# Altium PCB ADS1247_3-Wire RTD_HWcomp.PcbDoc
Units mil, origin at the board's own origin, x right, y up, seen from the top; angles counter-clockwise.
Board outline 1500 x 2000 mil, 2 copper layers (TopLayer, BottomLayer); 40 components, 32 nets, 123 pads, 60 vias.
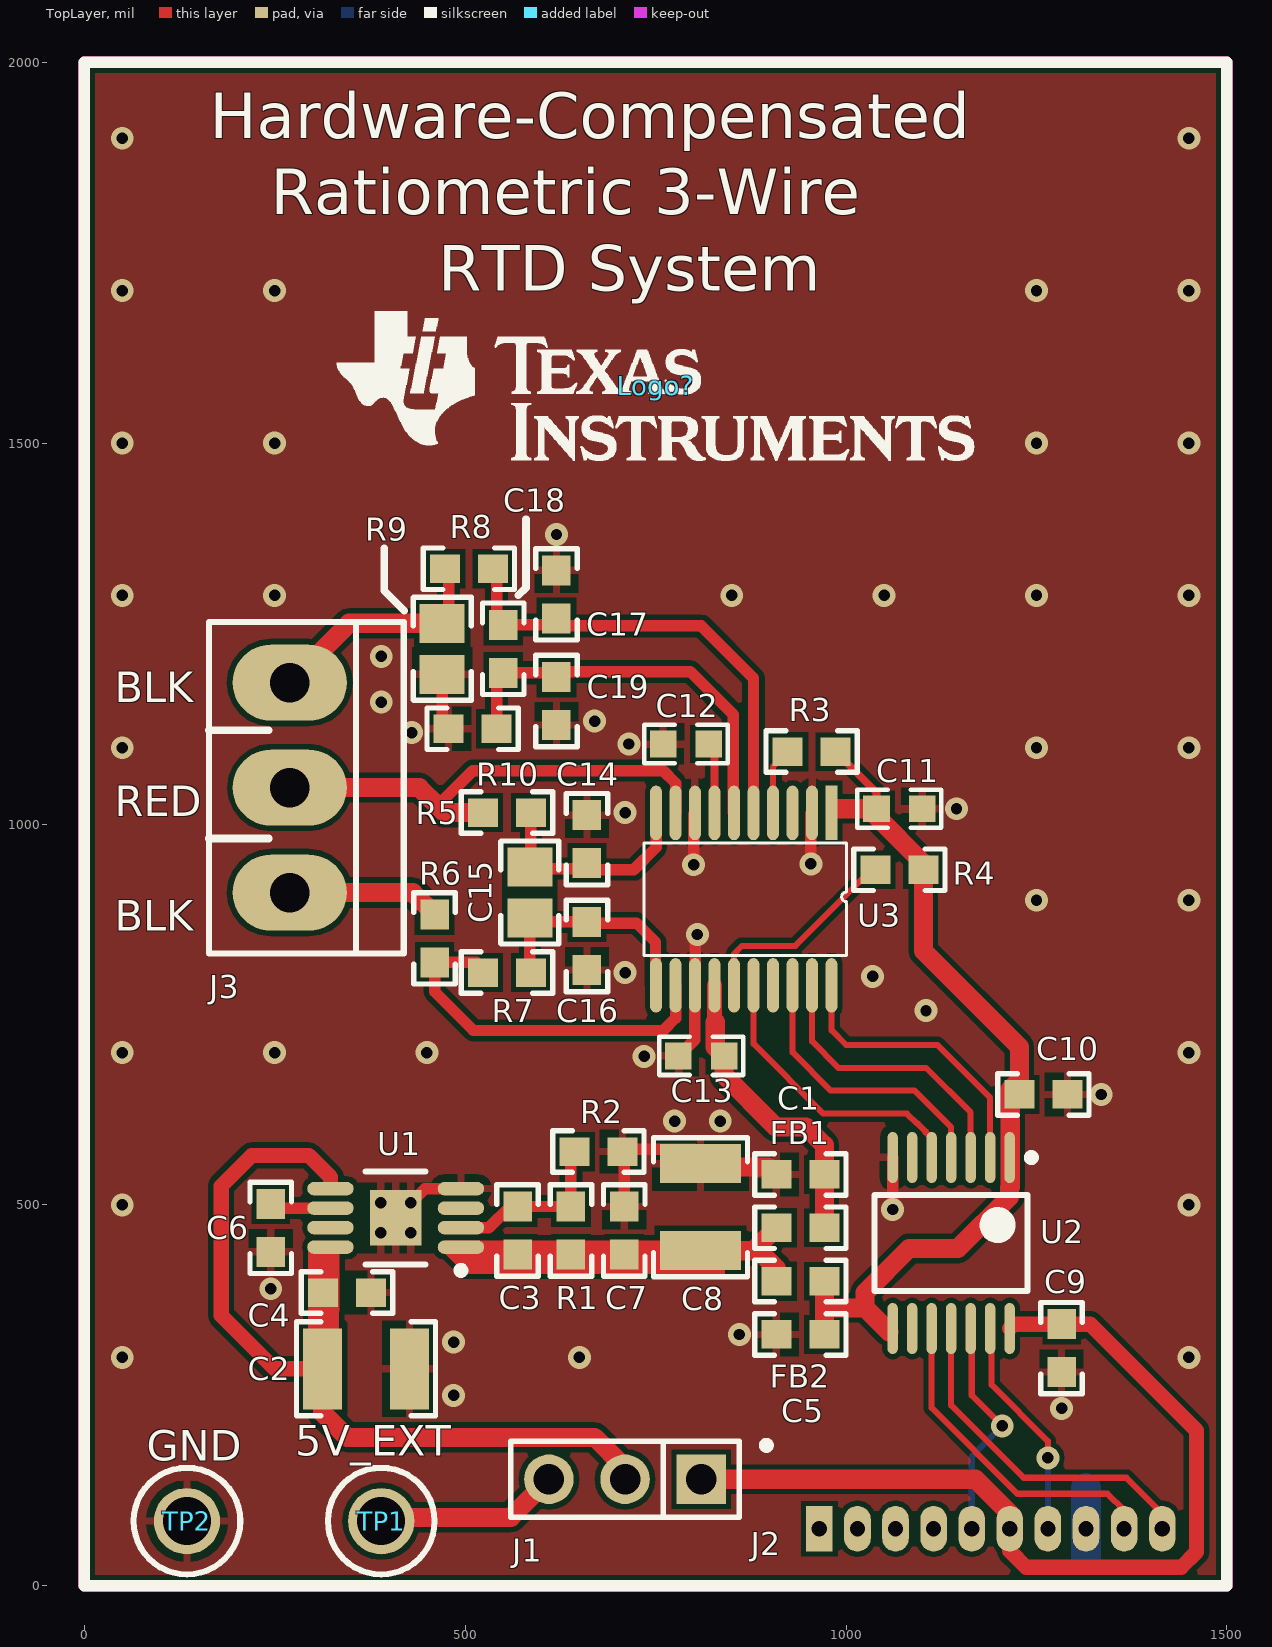
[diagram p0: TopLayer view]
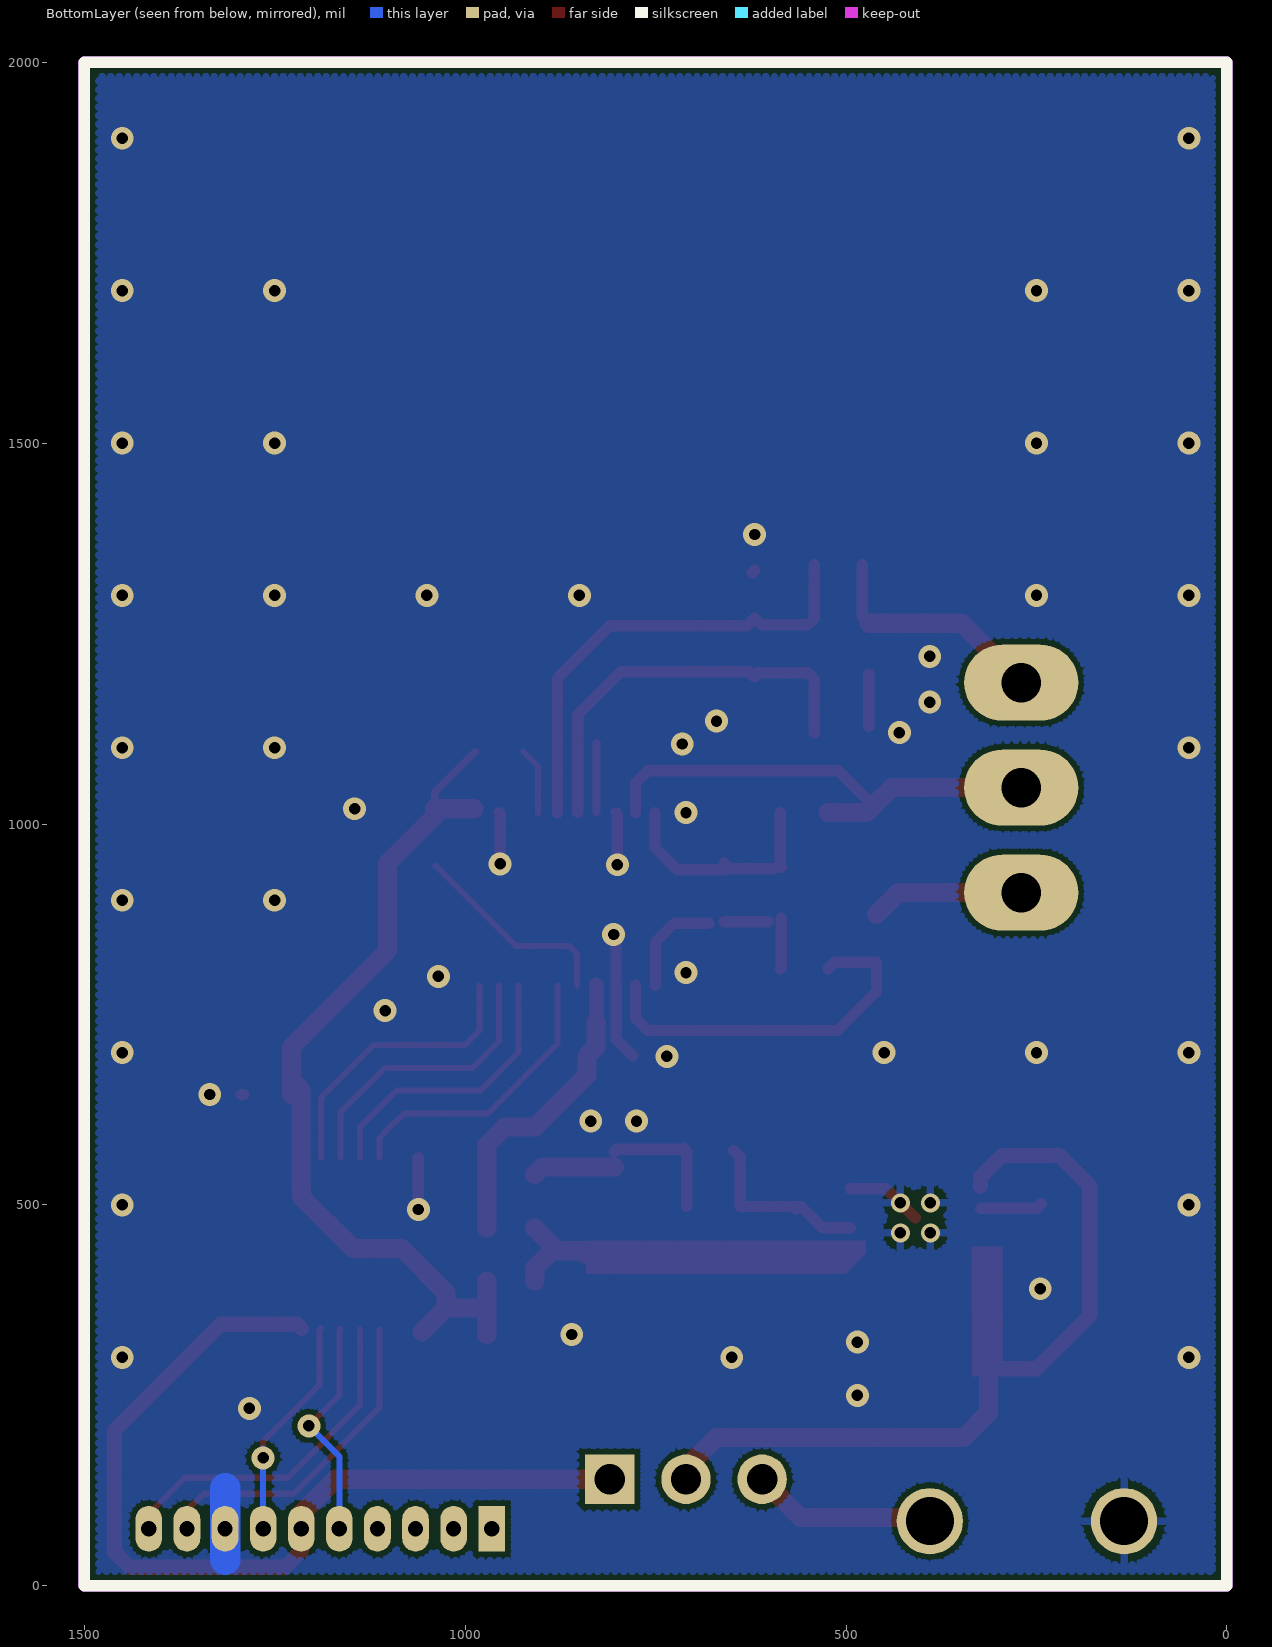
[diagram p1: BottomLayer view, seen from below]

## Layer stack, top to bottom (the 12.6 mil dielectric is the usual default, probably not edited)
TopLayer: signal copper 1.4
Dielectric: dielectric 12.6, FR-4, Dk 4.8
BottomLayer: signal copper 1.4

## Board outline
0,0 1500,0 1500,2000 0,2000

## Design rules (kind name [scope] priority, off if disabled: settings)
Clearance [All] p1: gap=7
ComponentClearance [All] p1: gap=7 collisioncheckmode=3 verticalgap=10 showdistances=FALSE
FabricationTestPointUsage TestPointUsage [All] p1: valid=0 allowmultiple=FALSE
FabricationTestpoint Testpoint [All] p1: side=3 testpointundercomponent=TRUE minsize=40 maxsize=100 preferedsize=60 minholesize=20 maxholesize=40 preferedholesize=32 testpointgrid=1 allowsidetop=TRUE allowsidebottom=TRUE usegrid=TRUE gridtolerance=0.01
PolygonConnect PolygonConnect_1 [(InComponentClass('All Components'))] p1: connectstyle=Relief reliefconductorwidth=10 reliefentries=4 polygonreliefangle="90 Angle" airgapwidth=10
PolygonConnect [All] p2: connectstyle=Direct reliefconductorwidth=15 reliefentries=4 polygonreliefangle="90 Angle" airgapwidth=7
RoutingVias [All] p1: holewidth=28 width=50 viastyle="Through Hole" minholewidth=28 minwidth=50 maxholewidth=28 maxwidth=50
SilkscreenOverComponentPads [All] p1: minsilkscreentomaskgap=10
SolderMaskExpansion [All] p1: expansion=4
Width [All] p1: maxlimit=200 minlimit=6 preferedwidth=12
24 further rules are at their usual default settings.

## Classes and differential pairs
component class Logo: Logo?
component class Header: J1

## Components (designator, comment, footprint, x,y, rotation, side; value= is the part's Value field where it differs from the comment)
C1 "GRM188R71H104KA93D" 0603#1 940,540 r180 top
C2 "C3225X7R1E106M" 1210 370,285 r0 top
C3 "C0603C103J5RACTU" 0603#1 569,466.5 r90 top
C4 "GRM188R71H104KA93D" 0603#1 345,385 r0 top
C5 "GRM188R71H104KA93D" 0603#1 940,330 r180 top
C6 "C0603C103J5RACTU" 0603#1 245,470 r270 top
C7 "GRM188R71H104KA93D" 0603#1 709,466.5 r90 top
C8 "C3225X7R1E106M" 1210 809,497 r90 top
C9 "GRM188R71H104KA93D" 0603#1 1283,312 r270 top
C10 "GRM188R71H104KA93D" 0603#1 1259,645 r0 top
C11 "GRM188R71H104KA93D" 0603#2 1070,1020 r180 top
C12 "C1608X7R1C105K" 0603#2 790,1105 r0 top
C13 "GRM188R71H104KA93D" 0603#2 810,695.59 r0 top
C14 "CL10C332JA8NNNC" 0603#1 660,980 r270 top
C15 "C2012C0G1E333J125AA" 0805 585,910 r90 top
C16 "CL10C332JA8NNNC" 0603#1 660,840 r90 top
C17 "GRM1885C1E152JA01D" 0603#1 620,1301.5 r270 top
C18 "C0603C153J3GACTU" 0603#1 550,1230 r270 top
C19 "GRM1885C1E152JA01D" 0603#1 620,1161.5 r90 top
FB1 "BLM18HG601SN1D" 0603#1 940,470 r0 top
FB2 "BLM18HG601SN1D" 0603#1 940,400 r0 top
J1 "TSW-103-07-G-S" TSW-103-07-G-S 710,140 r180 top
J2 "CON10" "DIP - 0.5 - 10" 965.24,75 r90 top
J3 "3POS_JUMPER" 3TERM_SCREW_CON_3.5MM 270,910 r90 top
Logo? "Texas Instruments" TI_Stacked_Overlay_Small 750,1575 r0 top
R1 "ERA-3AEB1653V" 0603#1 639,466.5 r90 top
R2 "RG1608P-5112-B-T5" 0603#1 675,570 r180 top
R3 "CRCW06031K00JNEA" 0603#1 955,1095 r0 top
R4 "CRCW06031K00JNEA" 0603#1 1070,940 r0 top
R5 "RC0603FR-0710KL" 0603#1 555,1015 r0 top
R6 "RG1608P-121-B-T5" 0603#1 460,850 r270 top
R7 "RC0603FR-0710KL" 0603#1 555,805 r0 top
R8 "RC0603FR-0720KL" 0603#1 505,1335 r180 top
R9 "RG2012L-332-L-T05" 0805 470,1230 r90 top
R10 "RC0603FR-0720KL" 0603#1 510,1125 r180 top
TP1 "5V_EXT" Keystone5005 390,85 r270 top
TP2 "GND" Keystone5006 135,85 r0 top
U1 "TPS7A4901" MUY08A_N 409,483 r180 top
U2 "TXS0104E" MTC14_N 1138,450 r270 top
U3 "ADS1247" 20-TSSOP(PW) 981,1014.59 r270 top

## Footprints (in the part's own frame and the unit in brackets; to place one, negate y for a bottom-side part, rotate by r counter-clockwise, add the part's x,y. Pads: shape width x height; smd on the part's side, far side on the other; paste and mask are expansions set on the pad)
3TERM_SCREW_CON_3.5MM [mil]
  oval 100x150 hole 52: 1(0,0) 2(137.79,0) 3(275.59,0)
  silkscreen extent -80,-150 355,106
20-TSSOP(PW) [mm] "TSOP, 8-Leads, Body 3x3mm, Pitch 0.65mm, Exposed Pad, IPC Medium Density"
  rect 1.82x0.39 smd: 1(0,0)
  oval 1.82x0.39 smd: 2(0,-0.65) 3(0,-1.3) 4(0,-1.95) 5(0,-2.6) 6(0,-3.25) 7(0,-3.9) 8(0,-4.55) 9(0,-5.2) 10(0,-5.85) 11(5.75,-5.85) 12(5.75,-5.2) 13(5.75,-4.55) 14(5.75,-3.9) 15(5.75,-3.25) 16(5.75,-2.6) 17(5.75,-1.95) 18(5.75,-1.3) 19(5.75,-0.65) 20(5.75,0)
  silkscreen extent 1,-6.25 4.75,0.5
0603#1 [mm] "0603 from SM-752 data"
  rect 1x0.95 smd: 1(-0.8,0) 2(0.8,0)
  silkscreen extent -1.52,-0.69 1.52,0.69, body extent -0.87,-0.47 0.87,0.47, height 0.85
0603#2 [mm]
  rect 0.889x0.889 smd: 1(-0.762,0) 2(0.762,0)
  silkscreen extent -1.4,-0.64 1.4,0.64
0805 [mm] "0805 from SM-752 data"
  rect 1.3x1.5 smd: 1(-0.85,0) 2(0.85,0)
  silkscreen extent -1.72,-0.97 1.72,0.97, body extent -1.1,-0.72 1.1,0.72, height 1.1
1210 [mm] "1210 from SM-752 data"
  rect 1.3x2.7 smd: 1(-1.45,0) 2(1.45,0)
  silkscreen extent -2.32,-1.57 2.32,1.57, body extent -1.7,-1.35 1.7,1.35, height 1.35
"DIP - 0.5 - 10" [mil]
  rect 60x35 hole 20: 1(0,0.24)
  oval 60x35 hole 20: 2(0,-49.76) 3(0,-99.76) 4(0,-149.76) 5(0,-199.76) 6(0,-249.76) 7(0,-299.76) 8(0,-349.76) 9(0,-399.76) 10(0,-449.76)
Keystone5005 [mil] "Keystone Compact loops"
  round 87 hole 63: 1(0,0)
  silkscreen extent -70,-70 70,70, body extent -63,-63 62,63, height 225
Keystone5006 [mil] "Keystone Compact loops"
  round 87 hole 63: 1(0,0)
  silkscreen extent -70,-70 70,70, body extent -63,-63 62,63, height 225
MTC14_N [mm] "TSOP, 14-Leads, Body 5x4.4mm, Pitch 0.65mm, IPC Medium Density"
  oval 1.7x0.35 smd: 1(-2.85,1.95) 2(-2.85,1.3) 3(-2.85,0.65) 4(-2.85,0) 5(-2.85,-0.65) 6(-2.85,-1.3) 7(-2.85,-1.95) 8(2.85,-1.95) 9(2.85,-1.3) 10(2.85,-0.65) 11(2.85,0) 12(2.85,0.65) 13(2.85,1.3) 14(2.85,1.95)
  silkscreen extent -2.97,-2.55 1.6,2.8, body extent -2.25,-2.55 2.25,2.55, height 1.1
MUY08A_N [mm] "TSOP, 8-Leads, Body 3x3mm, Pitch 0.65mm, Exposed Pad, IPC Medium Density"
  oval 1.55x0.45 smd: 1(-2.175,0.975) 2(-2.175,0.325) 3(-2.175,-0.325) 4(-2.175,-0.975) 5(2.175,-0.975) 6(2.175,-0.325) 7(2.175,0.325) 8(2.175,0.975)
  rect 1.73x1.85 smd: 9(0,0)
  silkscreen extent -2.3,-1.55 1,1.87, body extent -1.55,-1.55 1.55,1.55, height 1.09
TI_Stacked_Overlay_Small [mil]
  silkscreen extent -418,-98 418,98
TSW-103-07-G-S [mm] "Samtec 100mil, 1x3, 230 mil above insulator"
  rect 1.65x1.65 hole 1.016 mask+0: 1(-2.54,0)
  round 1.65 hole 1.016 mask+0: 2(0,0) 3(2.54,0)
  silkscreen extent -4.84,-1.27 3.81,1.27, body extent -3.81,-1.27 3.81,1.27, height 8.38

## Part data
C1 C4 C5 C7 C9 C10 C11 C13: "CAP, CERM, 0.1uF, 50V, +/-10%, X7R, 0603"
C2 C8: "CAP, CERM, 10uF, 25V, +/-20%, X7R, 1210"
C3 C6: "CAP, CERM, 0.01uF, 50V, +/-5%, X7R, 0603"
C12: "CAP, CERM, 1uF, 16V, +/-10%, X7R, 0603"
C14 C16: library part C1608C0G1H332J, "'CAP CER 3300PF 25V 5% NP0 0603"
C15: library part C2012C0G1E333J, "CAP CER 0.033UF 25V 5% NP0 0805"
C17 C19: library part C1608C0G1H152J, "CAP CER 1500PF 25V 5% NP0 0603"
C18: library part GRM188R71E153KA01D, "CAP CER 0.015UF 25V 5% NP0 0603"
FB1 FB2: library part Ferrite_Bead, "FERRITE CHIP 600 OHM 200MA 0603"
J1: "Header, TH, 100mil, 3x1, Gold plated, 230 mil above insulator"
J2: "Connector"
J3: library part RTD-3-WIRE
Logo?: library part TI_Logo, "Texas Instrument Corporate Signature"
R1: library part RT0603BRD07164KL, "RES 165K OHM 1/10W .1% 0603 SMD"
R2: "RES, 51.1k ohm, 0.1%, 0.1W, 0603"
R3 R4: "RES, 1.0k ohm, 5%, 0.1W, 0603"
R5 R7: "RES, 10.0k ohm, 1%, 0.1W, 0603"
R6: "RES, 120 ohm, 0.1%, 0.1W, 0603"
R8 R10: "RES, 20.0k ohm, 1%, 0.1W, 0603"
R9: library part RG2012P-822-B-T5, "RES 3.3K OHM 0.1W 0.01% 0805"
TP1: library part 5005, "Test Point, TH, Compact, Red"
TP2: library part 5006, "Test Point, TH, Compact, Black"
U1: "IC REG LDO ADJ .15A 8MSOP"

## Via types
v1: diameter 30, hole 15, TopLayer to BottomLayer, 56 vias
v2: diameter 25, hole 15, TopLayer to BottomLayer, 4 vias

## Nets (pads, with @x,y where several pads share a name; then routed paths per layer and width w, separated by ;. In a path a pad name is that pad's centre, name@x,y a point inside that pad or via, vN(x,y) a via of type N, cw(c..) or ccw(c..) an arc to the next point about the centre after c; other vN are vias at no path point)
AVDD: C1.1 C13.2 FB1.2 U3.14 | length 401.3
  TopLayer w20: U3.14 827.46,740.91 828.37,740
  TopLayer w25: 828.37,740 828.37,707.22 C13.2 840,670 907.5,602.5 947.5,602.5 971.5,578.5 FB1.2
DVDD: C5.1 C10.1 C11.2 FB2.2 R3.2 R4.2 U2.1 U2.8 U3.1 | length 1189.8
  TopLayer w10: R3.2 1040,1041.5 C11.2 C11.2@1040,1010
  TopLayer w25: C5.1 971.5,365 ; FB2.2 971.5,365 ; U3.1@988,1020 C11.2 ; C11.2@1040,1010 1101.5,948.5 1101.5,833.5 1227.5,707.5 C10.1@1227.5,663.5 ; U2.8@1056.5,333.5 1025,365 ; C10.1 C10.1@1227.5,663.5 ; 971.5,365 1025,365 ; 1025,365 1025,385 1083,443 1147,443 1214.77,510.77 1214.77,523.1 1215.57,523.9 1215.57,651.57 C10.1@1227.5,663.5
GND: C1.2 C2.2 C4.2 C5.2 C6.2 C7.2 C8.2 C9.2 C10.2 C11.1 C12.1 C13.1 C14.1 C16.1 C17.1 C19.1 J2.8 R2.1 R9.1 R10.2 TP2.1 U1.4 U1.9 U2.7 U3.2 U3.8 U3.13 | length 919.7
  TopLayer w15: U1.9 447.39,521.39 U1.4 ; R10.2@470,1128.5 R9.1 ; C17.1 C17.1@622.99,1330 ; C7.2 709,570.01 R2.1@713.74,574.75 ; R2.1@715.5,573 801,573 C8.2@804,570 ; C13.1 801.37,716.96 801.37,787.72 U3.13 v1@801.87,843.46 ; v1(800,946.59) 800,1012.72 U3.8 ; v1(954,947.59) 954,1013.18 U3.2 ; v1(1061.23,494) U2.7 ; C10.2 C10.2@1294,645
  TopLayer w25: C8.2@804,550.09 898.42,550.09 C1.2
  BottomLayer w25: 1313.1,130 1315,128.1 ; 1315,27 1315,34.5
  BottomLayer w40: 1315,34.5 J2.8 1315,128.1
  other v1: 1283,233 485,250 50,300 650,300 1450,300 485,320 860,330 245,390 50,500 1450,500 775,610 835,610 1335,645 735,695 50,700 250,700 450,700 1450,700 1105,755 1035,800 710,805 805,855 1250,900 1450,900 710,1015 1145,1020 50,1100 1250,1100 1450,1100 715,1105 430,1120 670,1135 390,1160 390,1220 50,1300 250,1300 850,1300 1050,1300 1250,1300 1450,1300 620,1380 50,1500 250,1500 1250,1500 1450,1500 50,1700 250,1700 1250,1700 1450,1700 50,1900 1450,1900
  other v2: 389.32,463.32 428.68,463.32 389.32,502.69 428.68,502.69
LDO_OUT: C3.1 C7.1 C8.1 FB1.1 FB2.1 R1.1 U1.1 | length 538.6
  TopLayer w25: U1.1@494.63,439.61 501.24,433 589,433 ; C3.1 R1.1 C7.1 804,435.01 804,435.91 C8.1@843.91,435.91 ; C8.1@808.91,439.91 C8.1 885.41,439.91 ; FB2.1 908.5,416.82 885.41,439.91 ; FB1.1 885.41,446.91 885.41,439.91
NetC2_1: C2.1 C4.1 J1.2 U1.5 U1.8 | length 1015.9
  TopLayer w20: C2.1 250,285 180,355 180,525 220,565 295,565 323.37,536.63 U1.5@323.37,524.15
  TopLayer w25: C2.1 312.91,227.09 345,195 670,195 710,155 J1.2
NetC3_2: C3.2 R1.2 R2.2 U1.2 | length 236.9
  TopLayer w15: U1.2 531.2,470.2 559,498 C3.2 ; C3.2@566.2,495.2 C3.2 ; R2.2@647.5,571.5 639,563 R1.2 C3.2
NetC6_1: C6.1 U1.6 | length 81.7
  TopLayer w15: C6.1@244,501.5 249.71,495.8 U1.6
NetC12_2: C12.2 U3.7 | length 92
  TopLayer w10: U3.7 C12.2@827.46,1106.59
NetC14_2: C14.2 C15.2 R5.2 U3.10 | length 288.2
  TopLayer w15: C15.2 586.5,944.96 R5.2 ; C15.2@595,941.5 652.99,941.5 C14.2 ; C14.2@660,940 721.41,940 750.68,969.28 U3.10
NetC15_1: C15.1 C16.2 R7.2 U3.11 | length 262.6
  TopLayer w15: C15.1 585,811.5 R7.2@586.5,810 ; C15.1@602.01,871.5 C16.2 ; 680,870 725,870 750,845 750,788.9 U3.11
NetJ1_3: J1.3 TP1.1 | length 240.7
  TopLayer w25: TP1.1@390,90 560,90 J1.3
NetJ2_1: J2.1
NetJ2_2: J2.2
NetJ2_3: J2.3
NetJ2_4: J2.4
NetJ2_5: J2.5 U2.12 | length 296.5
  TopLayer w8: U2.12 1165,336.39 1165,250 v1(1205,210)
  BottomLayer w8: J2.5 1165,170 v1(1205,210)
NetJ2_7: J2.7 U2.13 | length 337.2
  TopLayer w8: U2.13 1191,335.98 1191,264 1265,190 1265,160 v1(1265,168)
  BottomLayer w8: J2.7@1265,60 1265,65 v1@1265,180
NetJ2_9: J2.9 U2.10 | length 445.5
  TopLayer w8: U2.10@1112.41,336.8 1112.41,233.59 1225,121 1343,121 1365,99 J2.9 J2.9@1365,65
NetJ2_10: J2.10 U2.11 | length 465.6
  TopLayer w8: U2.11@1138,336.8 1138,237 1233,142 1368,142 1415,95 J2.10@1415,65
NetJ3_1: J3.1 R6.1 | length 201.8
  TopLayer w25: J3.1 431.5,910 R6.1
NetJ3_2: J3.2 R5.1 U3.9 | length 644.4
  TopLayer w15: 463.9,1023.9 510,1070 760,1070 776.28,1053.72 U3.9
  TopLayer w25: J3.2 440,1047.79 463.9,1023.9 472.79,1015 R5.1
NetJ3_3: J3.3 R8.2 R9.2 | length 312.3
  TopLayer w15: R9.2 478.5,1271.97 R8.2@478.5,1340
  TopLayer w25: J3.3 347.87,1263.46 R9.2
NetR3_1: R3.1 U3.4 | length 88.4
  TopLayer w8: U3.4 904.23,1075.72 R3.1
NetR4_1: R4.1 U3.15 | length 274.7
  TopLayer w8: U3.15 853.05,829.64 863.5,840.09 933.6,840.09 R4.1@1038.5,945
NetR6_2: R6.2 R7.1 U3.12 | length 492.6
  TopLayer w15: R7.1@523.5,810 515,818.5 R6.2 460,780 511,729 760,729 776.28,745.28 U3.12
NetU2_2: U2.2 U3.20 | length 382.5
  TopLayer w8: U3.20 981,729 1000,710 1120,710 1189.18,640.82 U2.2
NetU2_3: U2.3 U3.19 | length 379.6
  TopLayer w8: U3.19 955.41,714.59 990,680 1105,680 1163.59,621.41 U2.3
NetU2_4: U2.4 U3.18 | length 376.7
  TopLayer w8: U3.18 929.82,700.18 980,650 1090,650 1138,602 U2.4
NetU2_5: U2.5 U3.16 | length 387.8
  TopLayer w8: U3.16 878.64,711.36 970,620 1080,620 1093.33,606.67 1094.23,606.67 1104.71,596.19 1104.71,595.29 1112.41,587.59 U2.5
REFN: C18.2 C19.2 R10.1 U3.6 | length 540.5
  TopLayer w15: R10.1@541.5,1120 541.5,1190 C18.2 614.49,1198.5 C19.2 627.01,1200 795.59,1200 852,1143.59 U3.6@852,1015.64
REFP: C17.2 C18.1 R8.1 U3.5 | length 623.5
  TopLayer w15: R8.1@541.5,1340 541.5,1270 C18.1 611.5,1261.5 C17.2 630,1260 810,1260 878.64,1191.36 U3.5
VDUT: C9.1 J1.1 J2.6 U2.14 | length 1199.7
  TopLayer w20: U2.14 1220.47,343.5 C9.1 1320.5,343.5 1460,204 1460,44.5 1440,24.5 1236.5,24.5 1215,46 J2.6
  TopLayer w25: J1.1 1170,140 1215,95 J2.6
pads on no net: U1.3 U1.7 U2.6 U2.9 U3.3 U3.17
copper on no net: | length 14000
  TopLayer w15: 0,0 1500,0 1500,2000 0,2000 0,0
  BottomLayer w15: 0,0 1500,0 1500,2000 0,2000 0,0

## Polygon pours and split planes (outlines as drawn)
GND on BottomLayer "BottomLayer-REFN" (hatched 45Degree grid 8 track 8, remove dead copper, pour order 4): 0,2000 0,0 1500,0 1500,2000
GND on TopLayer "TopLayer-REFN" (solid, remove dead copper, pour order 2): 0,2000 0,0 1500,0 1500,2000

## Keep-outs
KeepOutLayer:
  lines w15: 1250,0 0,0 ; 0,0 0,2000 1500,2000 1500,0 0,0

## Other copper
TopLayer:
  region net NetC2_1: 335,445 334.06,275 294,275 294,445
  region net LDO_OUT: 474,453 840,453 841,452 841,410 500,410 474,436

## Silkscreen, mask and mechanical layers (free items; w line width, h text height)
TopOverlay:
  lines w10: 394,1362 394,1306 420,1280 ; 570,1300 580,1310 580,1400
  lines w15: 1250,0 0,0 ; 0,0 0,2000 1500,2000 1500,0 0,0
  text "Hardware-Compensated" at 165.19,1900 h60
  text "Ratiometric 3-Wire" at 245.16,1800 h60
  text "RTD System" at 465.09,1700 h60
  text "BLK" at 40,1160 h40
  text "RED" at 40,1010 h40
  text "BLK" at 40,860 h40
BottomOverlay:
  the board outline again, w15
TopSolder:
  the board outline again, w15
BottomSolder:
  the board outline again, w15
DrillDrawing:
  lines w10: -160,60 -140,0 ; -160,1940 -140,2000 ; -150,0 -130,0 ; -150,2000 -130,2000 ; -140,719.09 -140,0 ; -140,1280.91 -140,2000 ; -120,60 -140,0 ; -120,1940 -140,2000 ; 0,-150 0,-130 ; 60,-160 0,-140 ; 60,-120 0,-140 ; 474.08,-140 0,-140 ; 1025.92,-140 1500,-140 ; 1440,-160 1500,-140 ; 1440,-120 1500,-140 ; 1500,-150 1500,-130
  text "2000 (mil)" at -104.01,729.09 h60 r90
  text "1500 (mil)" at 484.08,-175.99 h60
